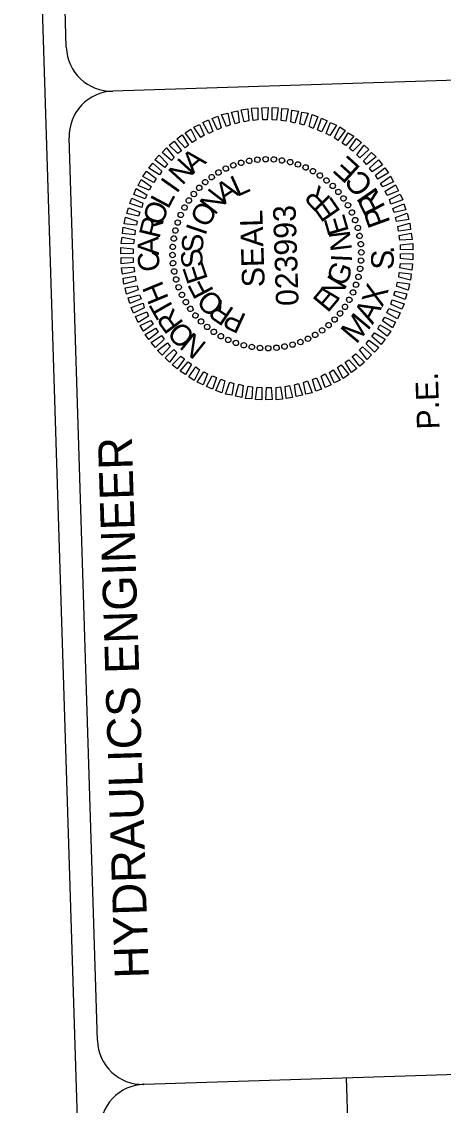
# Model space of a CAD drawing. Extents: x 2308163 to 2335412, y -96774 to 127732.
# Drawn here: x 2327102.4 to 2327242.4, y 124470.7 to 124830.2 of the extents above; entities that cross this region are included whole.
import ezdxf

# ---------------------------------------------------------------- set-up
doc = ezdxf.new("R2010")
doc.units = 0
for name, color, linetype in [('Sheet PE Seal Cell', 7, 'Continuous'), ('Sheet Title CELL', 7, 'Continuous'), ('Typical Detail Wedge2 CELL', 7, 'Continuous')]:
    doc.layers.add(name, color=color, linetype=linetype)

msp = doc.modelspace()

# ---------------------------------------------------------------- linework, layer by layer
at = {"layer": 'Sheet PE Seal Cell'}
for p, q in [((2327175.24, 124783.38), (2327175.24, 124783.38)), ((2327177.97, 124783.97), (2327177.97, 124783.97)), ((2327180.64, 124784.43), (2327180.64, 124784.43)), ((2327183.39, 124784.58), (2327183.39, 124784.58)), ((2327186.15, 124784.48), (2327186.15, 124784.48)), ((2327188.85, 124784.12), (2327188.85, 124784.12)), ((2327191.49, 124783.64), (2327191.49, 124783.64)), ((2327194.14, 124782.85), (2327194.14, 124782.85)), ((2327167.77, 124780.15), (2327167.77, 124780.15)), ((2327170.17, 124781.47), (2327170.17, 124781.47)), ((2327172.64, 124782.55), (2327172.64, 124782.55)), ((2327196.67, 124781.81), (2327196.67, 124781.81)), ((2327199.15, 124780.63), (2327199.15, 124780.63)), ((2327201.45, 124779.14), (2327201.45, 124779.14)), ((2327163.31, 124777), (2327163.31, 124777)), ((2327165.44, 124778.63), (2327165.44, 124778.63)), ((2327203.69, 124777.52), (2327203.69, 124777.52)), ((2327205.68, 124775.71), (2327205.68, 124775.71)), ((2327159.49, 124773.07), (2327159.49, 124773.07)), ((2327161.3, 124775.06), (2327161.3, 124775.06)), ((2327207.62, 124773.71), (2327207.62, 124773.71)), ((2327156.38, 124768.53), (2327156.38, 124768.53)), ((2327157.87, 124770.83), (2327157.87, 124770.83)), ((2327209.25, 124771.57), (2327209.25, 124771.57)), ((2327210.76, 124769.24), (2327210.76, 124769.24)), ((2327155.21, 124766.05), (2327155.21, 124766.05)), ((2327212.09, 124766.85), (2327212.09, 124766.85)), ((2327154.16, 124763.52), (2327154.16, 124763.52)), ((2327213.17, 124764.38), (2327213.17, 124764.38)), ((2327214, 124761.78), (2327214, 124761.78)), ((2327152.89, 124758.23), (2327152.89, 124758.23)), ((2327153.37, 124760.87), (2327153.37, 124760.87)), ((2327214.59, 124759.05), (2327214.59, 124759.05)), ((2327152.54, 124755.53), (2327152.54, 124755.53)), ((2327215.04, 124756.37), (2327215.04, 124756.37)), ((2327152.44, 124752.77), (2327152.44, 124752.77)), ((2327183.82, 124753.2), (2327183.82, 124753.2)), ((2327215.09, 124750.87), (2327215.09, 124750.87)), ((2327215.19, 124753.63), (2327215.19, 124753.63)), ((2327152.59, 124750.03), (2327152.59, 124750.03)), ((2327153.05, 124747.35), (2327153.05, 124747.35)), ((2327214.74, 124748.17), (2327214.74, 124748.17)), ((2327153.63, 124744.62), (2327153.63, 124744.62)), ((2327214.26, 124745.53), (2327214.26, 124745.53)), ((2327154.47, 124742.02), (2327154.47, 124742.02)), ((2327155.54, 124739.55), (2327155.54, 124739.55)), ((2327212.42, 124740.34), (2327212.42, 124740.34)), ((2327213.47, 124742.88), (2327213.47, 124742.88)), ((2327156.87, 124737.16), (2327156.87, 124737.16)), ((2327211.25, 124737.87), (2327211.25, 124737.87)), ((2327158.38, 124734.83), (2327158.38, 124734.83)), ((2327160.01, 124732.69), (2327160.01, 124732.69)), ((2327208.14, 124733.33), (2327208.14, 124733.33)), ((2327209.76, 124735.57), (2327209.76, 124735.57)), ((2327161.95, 124730.69), (2327161.95, 124730.69)), ((2327163.95, 124728.87), (2327163.95, 124728.87)), ((2327204.33, 124729.4), (2327204.33, 124729.4)), ((2327206.33, 124731.34), (2327206.33, 124731.34)), ((2327166.19, 124727.26), (2327166.19, 124727.26)), ((2327168.49, 124725.77), (2327168.49, 124725.77)), ((2327199.86, 124726.25), (2327199.86, 124726.25)), ((2327202.19, 124727.77), (2327202.19, 124727.77)), ((2327170.96, 124724.59), (2327170.96, 124724.59)), ((2327173.5, 124723.55), (2327173.5, 124723.55)), ((2327176.15, 124722.76), (2327176.15, 124722.76)), ((2327178.79, 124722.28), (2327178.79, 124722.28)), ((2327181.49, 124721.92), (2327181.49, 124721.92)), ((2327184.24, 124721.82), (2327184.24, 124721.82)), ((2327186.99, 124721.97), (2327186.99, 124721.97)), ((2327189.66, 124722.43), (2327189.66, 124722.43)), ((2327192.4, 124723.02), (2327192.4, 124723.02)), ((2327195, 124723.85), (2327195, 124723.85)), ((2327197.46, 124724.93), (2327197.46, 124724.93))]:
    msp.add_line(p, q, dxfattribs=at)
for points in [[(2327176.31, 124796.92), (2327175.31, 124800.96), (2327177.43, 124801.21), (2327177.8, 124797.22)], [(2327179.3, 124797.39), (2327178.67, 124801.44), (2327180.79, 124801.63), (2327180.79, 124797.56)], [(2327182.42, 124797.55), (2327182.1, 124801.61), (2327184.23, 124801.67), (2327183.92, 124797.6)], [(2327185.54, 124797.59), (2327185.54, 124801.65), (2327187.61, 124801.59), (2327187.05, 124797.51)], [(2327188.55, 124797.37), (2327188.8, 124801.38), (2327190.93, 124801.2), (2327190.06, 124797.11)], [(2327191.75, 124796.97), (2327192.13, 124800.86), (2327194.27, 124800.49), (2327193.08, 124796.51)], [(2327164.49, 124793.11), (2327162.5, 124796.74), (2327164.47, 124797.61), (2327165.84, 124793.78)], [(2327167.39, 124794.33), (2327165.64, 124798.09), (2327167.56, 124798.84), (2327168.68, 124794.99)], [(2327170.36, 124795.42), (2327168.79, 124799.37), (2327170.84, 124799.81), (2327171.65, 124795.9)], [(2327173.33, 124796.27), (2327172.02, 124800.16), (2327174.13, 124800.61), (2327174.63, 124796.68)], [(2327194.78, 124796.25), (2327195.47, 124800.15), (2327197.54, 124799.78), (2327196.11, 124795.8)], [(2327197.81, 124795.41), (2327198.81, 124799.32), (2327200.77, 124798.57), (2327199.14, 124794.77)], [(2327200.59, 124794.25), (2327201.91, 124798.17), (2327203.88, 124797.29), (2327201.99, 124793.67)], [(2327159.14, 124790.07), (2327156.67, 124793.3), (2327158.5, 124794.55), (2327160.37, 124790.98)], [(2327161.84, 124791.78), (2327159.54, 124795.21), (2327161.46, 124796.08), (2327163, 124792.56)], [(2327203.51, 124793.09), (2327204.96, 124796.7), (2327206.92, 124795.82), (2327204.72, 124792.38)], [(2327206.24, 124791.67), (2327208, 124795.23), (2327209.79, 124794.04), (2327207.4, 124790.71)], [(2327154.26, 124786.41), (2327151.35, 124789.19), (2327153, 124790.56), (2327155.48, 124787.32)], [(2327156.63, 124788.36), (2327153.91, 124791.34), (2327155.69, 124792.58), (2327157.8, 124789.15)], [(2327208.8, 124789.88), (2327210.82, 124793.32), (2327212.67, 124792.19), (2327210.01, 124789.1)], [(2327211.23, 124788.08), (2327213.57, 124791.41), (2327215.23, 124790.08), (2327212.38, 124787.24)], [(2327152.08, 124784.15), (2327149.06, 124786.75), (2327150.51, 124788.29), (2327153.05, 124785.12)], [(2327213.67, 124785.97), (2327216.14, 124789.24), (2327217.62, 124787.72), (2327214.71, 124785)], [(2327215.93, 124783.98), (2327218.59, 124786.81), (2327220.13, 124785.36), (2327216.84, 124782.82)], [(2327148.1, 124779.4), (2327144.59, 124781.6), (2327145.91, 124783.27), (2327148.94, 124780.61)], [(2327149.96, 124781.83), (2327146.63, 124784.29), (2327148.08, 124785.84), (2327150.86, 124783.05)], [(2327217.94, 124781.54), (2327220.85, 124784.32), (2327222.22, 124782.67), (2327218.79, 124780.38)], [(2327146.31, 124776.78), (2327142.61, 124778.85), (2327143.87, 124780.52), (2327147.01, 124778.18)], [(2327219.89, 124779.22), (2327223, 124781.64), (2327224.24, 124780.05), (2327220.68, 124777.87)], [(2327144.7, 124774.29), (2327141.08, 124775.86), (2327142.08, 124777.77), (2327145.41, 124775.5)], [(2327221.54, 124776.52), (2327224.84, 124778.94), (2327225.9, 124777.04), (2327222.33, 124775.36)], [(2327223.12, 124773.89), (2327226.56, 124775.99), (2327227.49, 124774.09), (2327223.73, 124772.53)], [(2327143.35, 124771.37), (2327139.61, 124772.82), (2327140.43, 124774.78), (2327143.99, 124772.77)], [(2327224.52, 124771.18), (2327228.09, 124772.92), (2327228.9, 124771.07), (2327224.94, 124769.63)], [(2327141.22, 124765.68), (2327137.31, 124766.49), (2327137.88, 124768.45), (2327141.61, 124767)], [(2327142.25, 124768.52), (2327138.27, 124769.84), (2327138.96, 124771.61), (2327142.64, 124769.97)], [(2327225.62, 124768.15), (2327229.32, 124769.7), (2327229.94, 124767.78), (2327226.1, 124766.85)], [(2327140.5, 124762.65), (2327136.42, 124763.15), (2327136.85, 124765.29), (2327140.77, 124763.97)], [(2327226.52, 124765.18), (2327230.42, 124766.61), (2327230.92, 124764.5), (2327226.88, 124763.87)], [(2327139.91, 124759.44), (2327135.89, 124759.88), (2327136.14, 124761.95), (2327140.05, 124760.95)], [(2327227.3, 124762.2), (2327231.27, 124763.32), (2327231.52, 124761.27), (2327227.54, 124760.71)], [(2327139.51, 124756.43), (2327135.44, 124756.55), (2327135.75, 124758.63), (2327139.71, 124757.94)], [(2327227.77, 124759.21), (2327231.75, 124760.03), (2327232.07, 124757.91), (2327228.01, 124757.72)], [(2327139.42, 124753.3), (2327135.36, 124753.17), (2327135.35, 124755.24), (2327139.43, 124754.8)], [(2327228.18, 124756.1), (2327232.24, 124756.54), (2327232.24, 124754.48), (2327228.17, 124754.6)], [(2327139.45, 124750.3), (2327135.4, 124749.86), (2327135.4, 124751.92), (2327139.46, 124751.8)], [(2327228.22, 124753.1), (2327232.28, 124753.23), (2327232.28, 124751.16), (2327228.2, 124751.6)], [(2327139.86, 124747.19), (2327135.88, 124746.37), (2327135.57, 124748.49), (2327139.62, 124748.68)], [(2327227.72, 124746.95), (2327231.74, 124746.52), (2327231.49, 124744.45), (2327227.58, 124745.45)], [(2327228.13, 124749.97), (2327232.2, 124749.85), (2327231.89, 124747.77), (2327227.93, 124748.46)], [(2327140.33, 124744.2), (2327136.36, 124743.07), (2327136.11, 124745.13), (2327140.09, 124745.69)], [(2327227.14, 124743.75), (2327231.22, 124743.25), (2327230.78, 124741.11), (2327226.86, 124742.42)], [(2327141.11, 124741.22), (2327137.22, 124739.79), (2327136.71, 124741.9), (2327140.76, 124742.53)], [(2327142.02, 124738.25), (2327138.31, 124736.7), (2327137.69, 124738.61), (2327141.54, 124739.55)], [(2327226.42, 124740.72), (2327230.32, 124739.91), (2327229.76, 124737.95), (2327226.02, 124739.4)], [(2327143.11, 124735.22), (2327139.54, 124733.48), (2327138.73, 124735.33), (2327142.69, 124736.77)], [(2327225.38, 124737.88), (2327229.36, 124736.56), (2327228.67, 124734.79), (2327224.99, 124736.43)], [(2327144.51, 124732.51), (2327141.08, 124730.4), (2327140.14, 124732.31), (2327143.91, 124733.87)], [(2327224.28, 124735.03), (2327228.02, 124733.58), (2327227.21, 124731.62), (2327223.64, 124733.63)], [(2327146.09, 124729.87), (2327142.79, 124727.46), (2327141.73, 124729.36), (2327145.31, 124731.04)], [(2327221.33, 124729.62), (2327225.02, 124727.55), (2327223.76, 124725.88), (2327220.62, 124728.22)], [(2327222.94, 124732.11), (2327226.55, 124730.53), (2327225.55, 124728.63), (2327222.23, 124730.9)], [(2327147.74, 124727.18), (2327144.63, 124724.76), (2327143.39, 124726.35), (2327146.95, 124728.53)], [(2327149.69, 124724.86), (2327146.78, 124722.08), (2327145.41, 124723.73), (2327148.84, 124726.02)], [(2327219.53, 124727), (2327223.04, 124724.8), (2327221.72, 124723.13), (2327218.7, 124725.78)], [(2327151.71, 124722.42), (2327149.05, 124719.59), (2327147.5, 124721.04), (2327150.8, 124723.58)], [(2327215.56, 124722.25), (2327218.58, 124719.65), (2327217.13, 124718.11), (2327214.59, 124721.28)], [(2327217.67, 124724.56), (2327221, 124722.11), (2327219.55, 124720.56), (2327216.77, 124723.35)], [(2327153.96, 124720.43), (2327151.5, 124717.16), (2327150.01, 124718.68), (2327152.93, 124721.4)], [(2327156.4, 124718.32), (2327154.07, 124714.99), (2327152.4, 124716.32), (2327155.25, 124719.16)], [(2327211, 124718.04), (2327213.72, 124715.06), (2327211.95, 124713.82), (2327209.84, 124717.25)], [(2327213.38, 124719.99), (2327216.28, 124717.2), (2327214.63, 124715.84), (2327212.16, 124719.08)], [(2327158.83, 124716.52), (2327156.82, 124713.08), (2327154.97, 124714.21), (2327157.62, 124717.29)], [(2327161.39, 124714.72), (2327159.63, 124711.17), (2327157.84, 124712.36), (2327160.24, 124715.69)], [(2327205.79, 124714.62), (2327208.09, 124711.19), (2327206.18, 124710.32), (2327204.63, 124713.84)], [(2327208.49, 124716.33), (2327210.97, 124713.1), (2327209.13, 124711.85), (2327207.27, 124715.42)], [(2327164.13, 124713.31), (2327162.68, 124709.7), (2327160.71, 124710.58), (2327162.92, 124714.02)], [(2327167.04, 124712.15), (2327165.72, 124708.23), (2327163.76, 124709.11), (2327165.64, 124712.73)], [(2327169.83, 124710.99), (2327168.82, 124707.08), (2327166.86, 124707.83), (2327168.49, 124711.63)], [(2327197.28, 124710.98), (2327198.84, 124707.02), (2327196.79, 124706.58), (2327195.98, 124710.5)], [(2327200.25, 124712.07), (2327201.99, 124708.31), (2327200.07, 124707.56), (2327198.95, 124711.41)], [(2327203.15, 124713.29), (2327205.14, 124709.66), (2327203.16, 124708.79), (2327201.79, 124712.62)], [(2327172.85, 124710.15), (2327172.16, 124706.25), (2327170.09, 124706.62), (2327171.53, 124710.6)], [(2327175.88, 124709.43), (2327175.5, 124705.54), (2327173.36, 124705.91), (2327174.55, 124709.89)], [(2327179.08, 124709.03), (2327178.83, 124705.02), (2327176.7, 124705.2), (2327177.57, 124709.29)], [(2327182.09, 124708.81), (2327182.09, 124704.75), (2327180.03, 124704.81), (2327180.59, 124708.89)], [(2327185.21, 124708.85), (2327185.53, 124704.79), (2327183.41, 124704.72), (2327183.71, 124708.8)], [(2327188.34, 124709.01), (2327188.96, 124704.96), (2327186.84, 124704.77), (2327186.84, 124708.84)], [(2327191.32, 124709.48), (2327192.32, 124705.44), (2327190.21, 124705.19), (2327189.83, 124709.18)], [(2327194.3, 124710.13), (2327195.61, 124706.24), (2327193.5, 124705.79), (2327193, 124709.72)]]:
    msp.add_lwpolyline(points, close=True, dxfattribs=at)
for centre, major_axis in [((2327172.68, 124782.51), (-0.32, 0.841)), ((2327175.28, 124783.36), (-0.245, 0.866)), ((2327177.94, 124783.99), (-0.169, 0.884)), ((2327180.65, 124784.39), (-0.091, 0.895)), ((2327183.38, 124784.55), (-0.013, 0.9)), ((2327186.11, 124784.47), (0.066, 0.898)), ((2327188.83, 124784.15), (0.144, 0.888)), ((2327191.5, 124783.59), (0.221, 0.873)), ((2327194.12, 124782.81), (0.296, 0.85)), ((2327196.67, 124781.8), (0.369, 0.821)), ((2327165.48, 124778.62), (-0.527, 0.73)), ((2327167.76, 124780.13), (-0.461, 0.773)), ((2327170.17, 124781.42), (-0.392, 0.81)), ((2327199.11, 124780.57), (0.439, 0.786)), ((2327201.44, 124779.13), (0.506, 0.744)), ((2327161.34, 124775.05), (-0.645, 0.627)), ((2327163.33, 124776.93), (-0.588, 0.681)), ((2327203.63, 124777.5), (0.569, 0.697)), ((2327205.67, 124775.68), (0.627, 0.645)), ((2327159.52, 124773.01), (-0.697, 0.569)), ((2327207.55, 124773.69), (0.681, 0.588)), ((2327209.24, 124771.54), (0.73, 0.527)), ((2327156.45, 124768.49), (-0.786, 0.439)), ((2327157.89, 124770.82), (-0.744, 0.506)), ((2327210.74, 124769.25), (0.773, 0.461)), ((2327155.22, 124766.05), (-0.821, 0.369)), ((2327212.04, 124766.85), (0.81, 0.392)), ((2327213.12, 124764.33), (0.841, 0.32)), ((2327153.42, 124760.89), (-0.873, 0.221)), ((2327154.21, 124763.51), (-0.85, 0.296)), ((2327213.98, 124761.74), (0.866, 0.245)), ((2327152.87, 124758.21), (-0.888, 0.144)), ((2327214.61, 124759.08), (0.884, 0.169)), ((2327152.55, 124755.49), (-0.898, 0.066)), ((2327215.01, 124756.37), (0.895, 0.091)), ((2327215.16, 124753.64), (0.9, 0.013)), ((2327152.47, 124752.76), (-0.9, -0.013)), ((2327152.63, 124750.03), (-0.895, -0.091)), ((2327215.08, 124750.91), (0.898, -0.066)), ((2327153.02, 124747.32), (-0.884, -0.169)), ((2327214.76, 124748.19), (0.888, -0.144)), ((2327153.65, 124744.66), (-0.866, -0.245)), ((2327213.42, 124742.89), (0.85, -0.296)), ((2327214.21, 124745.51), (0.873, -0.221)), ((2327154.51, 124742.06), (-0.841, -0.32)), ((2327155.59, 124739.55), (-0.81, -0.392)), ((2327212.41, 124740.35), (0.821, -0.369)), ((2327156.89, 124737.14), (-0.773, -0.461)), ((2327209.75, 124735.58), (0.744, -0.506)), ((2327211.18, 124737.91), (0.786, -0.439)), ((2327158.39, 124734.86), (-0.73, -0.527)), ((2327160.09, 124732.71), (-0.681, -0.588)), ((2327208.11, 124733.39), (0.697, -0.569)), ((2327161.96, 124730.72), (-0.627, -0.645)), ((2327164, 124728.9), (-0.569, -0.697)), ((2327202.16, 124727.77), (0.527, -0.73)), ((2327204.3, 124729.47), (0.588, -0.681)), ((2327206.29, 124731.35), (0.645, -0.627)), ((2327166.2, 124727.27), (-0.506, -0.744)), ((2327168.52, 124725.83), (-0.439, -0.786)), ((2327170.97, 124724.6), (-0.369, -0.821)), ((2327197.46, 124724.98), (0.392, -0.81)), ((2327199.87, 124726.27), (0.461, -0.773)), ((2327173.51, 124723.59), (-0.296, -0.85)), ((2327176.13, 124722.81), (-0.221, -0.873)), ((2327178.81, 124722.25), (-0.144, -0.888)), ((2327181.52, 124721.93), (-0.066, -0.898)), ((2327184.26, 124721.85), (0.013, -0.9)), ((2327186.99, 124722.01), (0.091, -0.895)), ((2327189.69, 124722.41), (0.169, -0.884)), ((2327192.36, 124723.03), (0.245, -0.866)), ((2327194.95, 124723.89), (0.32, -0.841))]:
    msp.add_ellipse(centre, major_axis=major_axis, ratio=0.999708, dxfattribs=at)
at = {"layer": 'Sheet Title CELL'}
for p, q in [((2327169.46, 122925.21), (2327102.37, 125054.15)), ((2327117.2, 124821.66), (2327109.87, 125054.39)), ((2327372.55, 124814.7), (2327132.67, 124807.14)), ((2327127.59, 124492.17), (2327118.15, 124791.67)), ((2327382.95, 124485.21), (2327143.07, 124477.65)), ((2327210.16, 124479.76), (2327224.55, 124022.49))]:
    msp.add_line(p, q, dxfattribs=at)
for centre, start, end in [((2327132.2, 124822.13), 181.8048, 271.8048), ((2327133.14, 124792.15), 91.8048, 181.8048), ((2327142.51, 124492.64), 181.8048, 271.8048), ((2327143.46, 124462.66), 91.8048, 181.8048)]:
    msp.add_arc(centre, 15, start, end, dxfattribs=at)

# ---------------------------------------------------------------- texts
at = {"layer": 'Sheet PE Seal Cell'}
for s, height, rotation, p in [('A', 7.05, 40.4219, (2327159.29, 124779.44)), ('N', 7.05, 47.6237, (2327155.72, 124775.64)), ('I', 7.05, 54.8249, (2327153.87, 124772.89)), ('A', 7.05, 33.5651, (2327169.67, 124769.39)), ('L', 7.05, 24.2056, (2327173.91, 124771.96)), ('R', 7.05, 134.2862, (2327205.44, 124771.51)), ('L', 7.05, 62.0257, (2327151.03, 124767.74)), ('N', 7.05, 52.2814, (2327166.54, 124765.72)), ('E', 7.05, 124.9289, (2327208.51, 124767.17)), ('O', 7.05, 69.226, (2327148.89, 124762.17)), ('O', 7.05, 61.6383, (2327164.17, 124761.46)), ('023993', 7.498, 91.8048, (2327194.37, 124735.99)), ('R', 7.05, 76.4259, (2327148.09, 124757.95)), ('SEAL', 7.498, 91.8048, (2327183.1, 124742.17)), ('E', 7.05, 106.2166, (2327211.16, 124760.63)), ('I', 7.05, 70.9944, (2327163.38, 124758.93)), ('A', 7.05, 90.8251, (2327148, 124752.7)), ('S', 7.05, 89.7052, (2327162.67, 124753.53)), ('N', 7.05, 96.8612, (2327212.1, 124754.47)), ('S', 7.05, 99.0604, (2327162.87, 124749.04)), ('C', 7.05, 98.0247, (2327148.53, 124747.77)), ('E', 7.05, 108.4159, (2327164.32, 124744.77)), ('I', 7.05, 87.506, (2327212.05, 124750.27)), ('G', 7.05, 68.795, (2327209.93, 124742.02)), ('H', 7.05, 112.4243, (2327151.33, 124738.36)), ('F', 7.05, 117.7718, (2327166.32, 124740.83)), ('N', 7.05, 59.4387, (2327207.27, 124737.18)), ('O', 7.05, 136.486, (2327170.14, 124736.82)), ('E', 7.05, 50.0817, (2327204.02, 124733.33)), ('T', 7.05, 119.6246, (2327153.52, 124734.36)), ('R', 7.05, 145.8444, (2327173.27, 124734.73)), ('R', 7.05, 126.8253, (2327156.4, 124730.2)), ('P', 7.05, 155.2037, (2327177.33, 124732.86)), ('O', 7.05, 134.0265, (2327160.41, 124726.01)), ('N', 7.05, 141.2283, (2327164.13, 124723.25))]:
    msp.add_text(s, height=height, rotation=rotation, dxfattribs=at).set_placement(p)
at = {"layer": 'Sheet Title CELL'}
for s, height, p in [('P.E.', 7.499, (2327241.17, 124695.02)), (' HYDRAULICS ENGINEER', 11.25, (2327144.72, 124508.76))]:
    msp.add_text(s, height=height, rotation=91.8048, dxfattribs=at).set_placement(p)
at = {"layer": 'Typical Detail Wedge2 CELL'}
for s, rotation, p in [('E', 137.8431, (2327215.26, 124781.61)), ('C', 128.2694, (2327219.54, 124775.99)), ('I', 124.4709, (2327220.98, 124773.57)), ('R', 116.9973, (2327223.31, 124768.56)), ('P', 109.8943, (2327224.91, 124763.56)), ('S', 88.3537, (2327225.84, 124747.75)), ('.', 95.6728, (2327226.19, 124753.15)), ('X', 70.5344, (2327222.16, 124735.15)), ('A', 61.702, (2327218.93, 124729.48)), ('M', 50.1827, (2327213.49, 124722.95))]:
    msp.add_text(s, height=7.5, rotation=rotation, dxfattribs=at).set_placement(p)

doc.saveas('drawing.dxf')
